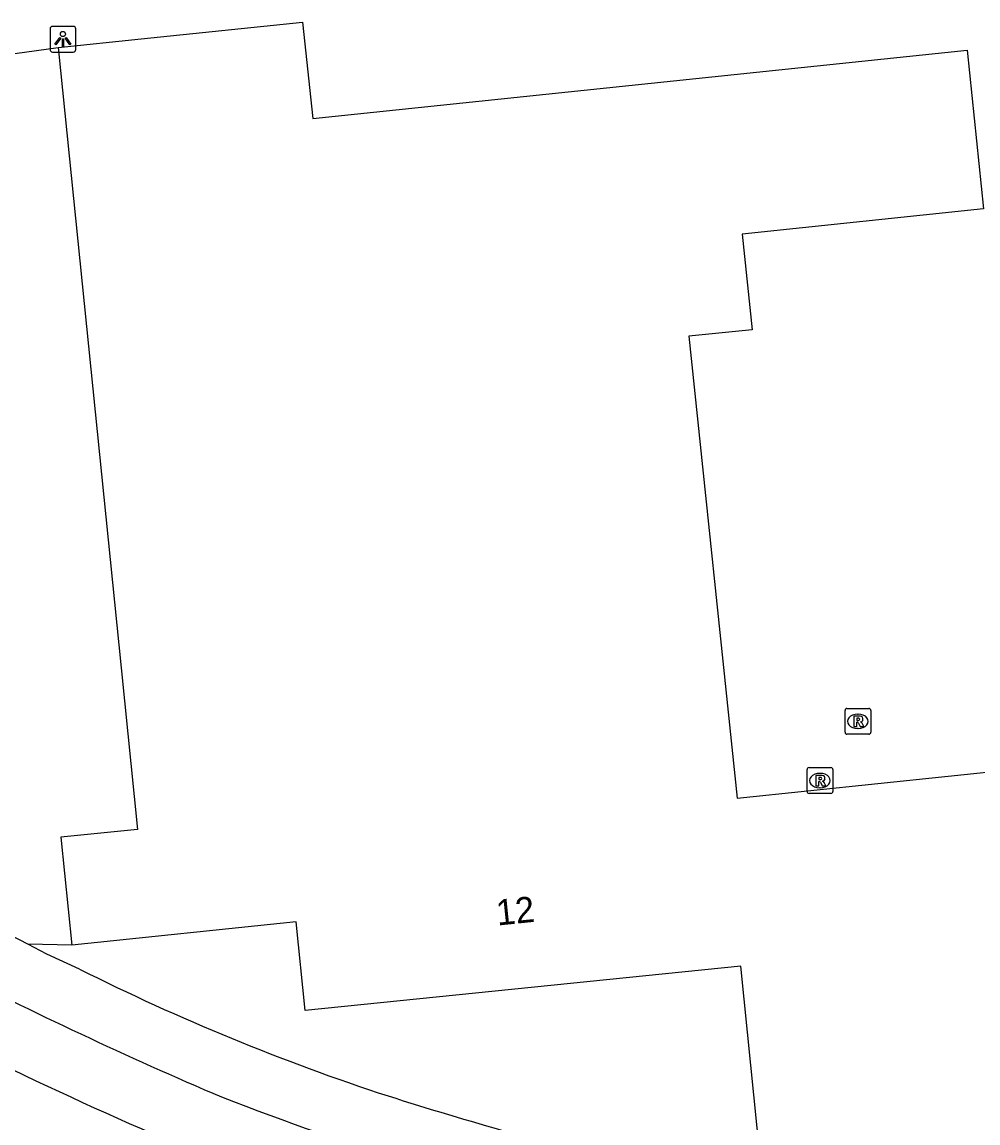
# Model space of a CAD drawing. Extents: x 160676 to 161153, y 383244 to 383713.
# Drawn here: x 160791.46 to 160828.58, y 383614.83 to 383657.57 of the extents above; entities that cross this region are included whole.
import ezdxf

# ---------------------------------------------------------------- set-up
doc = ezdxf.new("R2010")
doc.units = 0
for name, color, linetype in [('IMGEO_Fietspad_gesloten', 7, 'Continuous'), ('IMGEO_Hek', 7, 'Continuous'), ('IMGEO_Lichtpunt', 7, 'Continuous'), ('IMGEO_Pand', 7, 'Continuous'), ('IMGEO_Pand_nummerreeks', 7, 'Continuous'), ('IMGEO_Rioolput', 7, 'Continuous'), ('IMGEO_Voetpad_open', 7, 'Continuous')]:
    doc.layers.add(name, color=color, linetype=linetype)

msp = doc.modelspace()

# ---------------------------------------------------------------- linework, layer by layer
at = {"layer": 'IMGEO_Fietspad_gesloten'}
for centre, radius, start, end in [((160864.688, 383769.447), 166.981, 242.79969, 246.91356), ((160861.06, 383762.676), 161.697, 242.06214, 247.72017), ((160843.7, 383730.875), 123.34, 248.85646, 256.29581)]:
    msp.add_arc(centre, radius, start, end, dxfattribs=at)
at = {"layer": 'IMGEO_Hek'}
msp.add_lwpolyline([(160793.391, 383621.736), (160791.682, 383621.775)], dxfattribs=at)
at = {"layer": 'IMGEO_Lichtpunt'}
for p, q in [((160792.551, 383657.308), (160792.551, 383656.501)), ((160792.551, 383657.308), (160792.551, 383656.501)), ((160793.453, 383657.403), (160792.645, 383657.403)), ((160793.453, 383657.403), (160792.645, 383657.403)), ((160793.547, 383656.501), (160793.547, 383657.308)), ((160793.547, 383656.501), (160793.547, 383657.308)), ((160792.645, 383656.407), (160793.453, 383656.407)), ((160792.645, 383656.407), (160793.453, 383656.407))]:
    msp.add_line(p, q, dxfattribs=at)
for points in [[(160792.925, 383656.972), (160792.964, 383656.944), (160792.776, 383656.682), (160792.738, 383656.709), (160792.925, 383656.972)], [(160793.027, 383656.924), (160793.074, 383656.924), (160793.074, 383656.602), (160793.027, 383656.602), (160793.027, 383656.924)], [(160793.137, 383656.944), (160793.175, 383656.971), (160793.362, 383656.709), (160793.323, 383656.681), (160793.137, 383656.944)]]:
    msp.add_lwpolyline(points, dxfattribs=at)
msp.add_circle((160793.05, 383657.106), 0.0994, dxfattribs=at)
for centre, start, end in [((160792.645, 383657.308), 90, 180), ((160792.645, 383657.308), 90, 180), ((160793.453, 383657.308), 0, 90), ((160793.453, 383657.308), 0, 90), ((160792.645, 383656.501), 180, 270), ((160792.645, 383656.501), 180, 270), ((160793.453, 383656.501), 270, 0), ((160793.453, 383656.501), 270, 360)]:
    msp.add_arc(centre, 0.0946, start, end, dxfattribs=at)
at = {"layer": 'IMGEO_Pand'}
for points in [[(160792.87, 383656.581), (160796.093, 383656.918), (160802.355, 383657.572), (160802.747, 383653.821), (160828.156, 383656.475), (160828.799, 383650.321), (160819.421, 383649.342), (160819.809, 383645.628), (160817.356, 383645.372), (160819.229, 383627.443), (160830.158, 383628.584), (160830.446, 383625.822), (160859.515, 383628.858), (160859.14, 383632.451), (160866.054, 383633.173), (160867.696, 383617.451), (160865.631, 383617.236), (160866.271, 383611.111)], [(160792.87, 383656.581), (160795.304, 383632.499), (160795.95, 383626.229), (160792.973, 383625.928), (160793.391, 383621.736)], [(160866.271, 383611.111), (160838.875, 383608.305), (160838.299, 383613.926), (160820.27, 383612.085), (160819.369, 383620.919), (160802.453, 383619.202), (160802.104, 383622.635), (160793.391, 383621.736)]]:
    msp.add_lwpolyline(points, dxfattribs=at)
at = {"layer": 'IMGEO_Rioolput'}
for p, q in [((160823.417, 383629.996), (160823.417, 383630.848)), ((160823.492, 383630.922), (160824.344, 383630.922)), ((160823.905, 383630.702), (160823.93, 383630.702)), ((160824.418, 383630.848), (160824.418, 383629.996)), ((160824.344, 383629.922), (160823.492, 383629.922)), ((160823.928, 383630.142), (160823.903, 383630.142)), ((160821.943, 383627.698), (160821.943, 383628.55)), ((160822.018, 383628.624), (160822.87, 383628.624)), ((160822.944, 383628.55), (160822.944, 383627.698)), ((160822.431, 383628.404), (160822.456, 383628.404)), ((160822.87, 383627.624), (160822.018, 383627.624)), ((160822.454, 383627.844), (160822.429, 383627.844))]:
    msp.add_line(p, q, dxfattribs=at)
for points in [[(160823.417, 383629.996), (160823.417, 383630.848)], [(160823.492, 383630.922), (160824.344, 383630.922)], [(160824.006, 383630.62), (160823.754, 383630.622), (160823.754, 383630.222)], [(160824.418, 383630.848), (160824.418, 383629.996)], [(160823.754, 383630.222), (160823.878, 383630.222), (160823.878, 383630.384), (160823.889, 383630.384)], [(160823.932, 383630.541), (160823.878, 383630.541), (160823.878, 383630.46)], [(160823.878, 383630.46), (160823.93, 383630.46)], [(160823.936, 383630.355), (160824.007, 383630.222), (160824.147, 383630.222), (160824.082, 383630.348)], [(160824.344, 383629.922), (160823.492, 383629.922)], [(160821.943, 383627.698), (160821.943, 383628.55)], [(160822.018, 383628.624), (160822.87, 383628.624)], [(160822.944, 383628.55), (160822.944, 383627.698)], [(160822.532, 383628.322), (160822.28, 383628.324), (160822.28, 383627.924)], [(160822.28, 383627.924), (160822.404, 383627.924), (160822.404, 383628.086), (160822.415, 383628.086)], [(160822.458, 383628.243), (160822.404, 383628.243), (160822.404, 383628.162)], [(160822.404, 383628.162), (160822.456, 383628.162)], [(160822.462, 383628.057), (160822.533, 383627.924), (160822.673, 383627.924), (160822.608, 383628.05)], [(160822.87, 383627.624), (160822.018, 383627.624)]]:
    msp.add_lwpolyline(points, dxfattribs=at)
for centre, radius, start, end in [((160823.494, 383630.846), 0.0765, 91.552, 178.448), ((160823.494, 383630.846), 0.0765, 91.552, 178.448), ((160824.005, 383630.51), 0.109, 350.3612, 89.416), ((160824.342, 383630.846), 0.0765, 1.552, 88.448), ((160824.342, 383630.846), 0.0765, 1.552, 88.448), ((160823.888, 383630.331), 0.0533, 26.0293, 88.6989), ((160823.914, 383630.649), 0.19, 274.7715, 282.9687), ((160823.938, 383630.445), 0.0964, 77.0061, 93.1865), ((160823.952, 383630.502), 0.0378, 276.6634, 79.6772), ((160824.003, 383630.51), 0.112, 277.5842, 350.9817), ((160823.987, 383630.295), 0.108, 29.5134, 73.7905), ((160823.494, 383629.998), 0.0765, 181.552, 268.448), ((160823.494, 383629.998), 0.0765, 181.552, 268.448), ((160824.342, 383629.998), 0.0765, 271.552, 358.448), ((160824.342, 383629.998), 0.0765, 271.552, 358.448), ((160822.02, 383628.548), 0.0765, 91.552, 178.448), ((160822.02, 383628.548), 0.0765, 91.552, 178.448), ((160822.868, 383628.548), 0.0765, 1.552, 88.448), ((160822.868, 383628.548), 0.0765, 1.552, 88.448), ((160822.414, 383628.033), 0.0533, 26.0293, 88.6989), ((160822.44, 383628.351), 0.19, 274.7715, 282.9687), ((160822.464, 383628.147), 0.0964, 77.0061, 93.1865), ((160822.478, 383628.204), 0.0378, 276.6634, 79.6772), ((160822.531, 383628.212), 0.109, 350.3612, 89.416), ((160822.529, 383628.212), 0.112, 277.5842, 350.9817), ((160822.513, 383627.997), 0.108, 29.5134, 73.7905), ((160822.02, 383627.7), 0.0765, 181.552, 268.448), ((160822.02, 383627.7), 0.0765, 181.552, 268.448), ((160822.868, 383627.7), 0.0765, 271.552, 358.448), ((160822.868, 383627.7), 0.0765, 271.552, 358.448)]:
    msp.add_arc(centre, radius, start, end, dxfattribs=at)
for centre, major_axis, ratio, start_param, end_param in [((160823.904, 383630.422), (-0.387, 0.002), 0.722429, 4.712389, 7.853982), ((160823.929, 383630.422), (-0.39, 0.002), 0.717154, 1.570796, 4.712389), ((160822.43, 383628.124), (-0.387, 0.002), 0.722429, 4.712389, 7.853982), ((160822.455, 383628.124), (-0.39, 0.002), 0.717154, 1.570796, 4.712389)]:
    msp.add_ellipse(centre, major_axis=major_axis, ratio=ratio, start_param=start_param, end_param=end_param, dxfattribs=at)
at = {"layer": 'IMGEO_Voetpad_open'}
for points in [[(160780.43, 383643.95), (160784.026, 383649.959), (160789.026, 383656.053), (160792.87, 383656.581)], [(160791.682, 383621.775), (160774.063, 383630.917)], [(160793.391, 383621.736), (160791.682, 383621.775)], [(160793.688, 383620.806), (160792.429, 383621.388), (160791.682, 383621.775)]]:
    msp.add_lwpolyline(points, dxfattribs=at)
for centre, radius, start, end in [((160833.055, 383699.547), 88.034, 243.43733, 251.88316), ((160855.841, 383774.237), 166.113, 252.42406, 255.80558)]:
    msp.add_arc(centre, radius, start, end, dxfattribs=at)

# ---------------------------------------------------------------- texts
at = {"layer": 'IMGEO_Pand_nummerreeks'}
msp.add_text('12', height=1, rotation=5.7983, dxfattribs=at).set_placement((160809.921, 383622.493))

doc.saveas('drawing.dxf')
